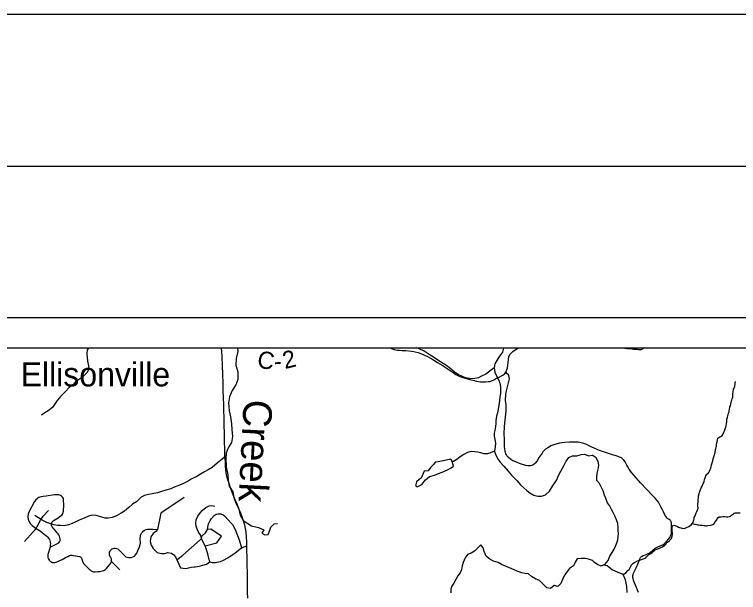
# Model space of a CAD drawing. Extents: x 0 to 34, y 0 to 22.
# Drawn here: x 3.746 to 6.132, y 20.093 to 22 of the extents above; entities that cross this region are included whole.
import ezdxf

# ---------------------------------------------------------------- set-up
doc = ezdxf.new("R2010")
doc.units = 0
for name, color, linetype in [('GM_X_County_Road', 7, 'Continuous'), ('GM_X_County_Road_Text', 7, 'Continuous'), ('GM_X_Major_River', 7, 'Continuous'), ('GM_X_Minor_Lake', 7, 'Continuous'), ('GM_X_Minor_River', 7, 'Continuous'), ('GM_X_Minor_River_Text', 7, 'Continuous'), ('GM_X_State_Route', 7, 'Continuous'), ('GM_X_Township_Road', 7, 'Continuous'), ('GM_X_Unincorporated_Text', 7, 'Continuous'), ('SH_Border', 7, 'Continuous'), ('SH_Cut_Line', 7, 'Continuous'), ('SH_Data', 7, 'Continuous')]:
    doc.layers.add(name, color=color, linetype=linetype)

msp = doc.modelspace()

# ---------------------------------------------------------------- linework, layer by layer
at = {"layer": 'GM_X_County_Road'}
for points in [[(4.9846, 20.9), (4.9915, 20.8969), (4.9974, 20.895), (5.0027, 20.8939), (5.0086, 20.8928), (5.0149, 20.8923), (5.0229, 20.8916), (5.0355, 20.8912), (5.0545, 20.8896), (5.0625, 20.8884), (5.0663, 20.8874), (5.0767, 20.8846), (5.0881, 20.8804), (5.0956, 20.8768), (5.1075, 20.8713), (5.1251, 20.8619), (5.1406, 20.8524), (5.1554, 20.8434), (5.1692, 20.8341), (5.1922, 20.8187), (5.2011, 20.8128), (5.2123, 20.8072), (5.2174, 20.8045), (5.2239, 20.8022), (5.232, 20.7997), (5.2469, 20.7961), (5.2572, 20.7937)], [(5.3657, 20.8196), (5.3707, 20.8332), (5.374, 20.8613), (5.3757, 20.8718), (5.3799, 20.8799), (5.3884, 20.8884), (5.4057, 20.9)], [(5.2572, 20.7937), (5.2693, 20.7908), (5.2759, 20.7894), (5.282, 20.7883), (5.2905, 20.7876), (5.2987, 20.7882), (5.3072, 20.7888), (5.3127, 20.7894), (5.3211, 20.7924), (5.3281, 20.796), (5.335, 20.7997), (5.3367, 20.8004), (5.3552, 20.8104), (5.36, 20.8133), (5.3624, 20.8155), (5.3657, 20.8196)], [(5.9114, 20.3196), (5.9114, 20.3205), (5.9112, 20.3228), (5.9107, 20.3248), (5.91, 20.327), (5.9088, 20.3293), (5.9071, 20.3316), (5.9041, 20.334), (5.8993, 20.3363), (5.8971, 20.3387), (5.8942, 20.3423), (5.891, 20.3463), (5.8892, 20.3492), (5.8847, 20.3593), (5.8816, 20.3661), (5.8778, 20.3738), (5.8723, 20.3844), (5.8682, 20.3908), (5.8633, 20.3979), (5.8576, 20.4047), (5.8495, 20.4127), (5.8317, 20.4317), (5.8094, 20.4547), (5.7881, 20.4788), (5.7808, 20.4879), (5.776, 20.4939), (5.7718, 20.5003), (5.7682, 20.5072), (5.7647, 20.5131), (5.7585, 20.5237), (5.7547, 20.5292), (5.7519, 20.5324), (5.747, 20.537), (5.7436, 20.5385), (5.733, 20.5428), (5.7256, 20.5449), (5.7209, 20.5465), (5.6904, 20.556), (5.6745, 20.5614), (5.6488, 20.5728), (5.6288, 20.5821), (5.6225, 20.5845), (5.6179, 20.5861), (5.6142, 20.5872), (5.6092, 20.5883), (5.6035, 20.5888), (5.5959, 20.5895), (5.5892, 20.5895), (5.5802, 20.5892), (5.575, 20.5892), (5.5599, 20.5883), (5.5503, 20.5871), (5.5421, 20.5857), (5.5303, 20.5827), (5.52, 20.5793), (5.5144, 20.5771), (5.5092, 20.5741), (5.5038, 20.5707), (5.4968, 20.5656), (5.4943, 20.5634), (5.4879, 20.5568), (5.4848, 20.5533), (5.4759, 20.5398), (5.4683, 20.5275), (5.4626, 20.5202), (5.4589, 20.5163), (5.4554, 20.5139), (5.4513, 20.5121), (5.4467, 20.5113), (5.4413, 20.5109), (5.4377, 20.5111), (5.4312, 20.512), (5.4285, 20.5128), (5.4235, 20.5143), (5.4111, 20.5185), (5.4002, 20.5227), (5.3926, 20.5261), (5.3885, 20.5279), (5.3823, 20.5315), (5.3732, 20.5395), (5.3701, 20.5432), (5.3678, 20.5471), (5.3659, 20.5508), (5.3646, 20.5553), (5.3633, 20.5606), (5.3625, 20.5666), (5.3617, 20.5735), (5.3613, 20.5986), (5.3596, 20.6163), (5.3611, 20.6413), (5.3671, 20.6921), (5.3664, 20.7134), (5.3644, 20.7271), (5.366, 20.7479), (5.3677, 20.7585), (5.3731, 20.7802), (5.3772, 20.7984), (5.377, 20.8035), (5.3756, 20.8074), (5.374, 20.8114), (5.3697, 20.814), (5.3657, 20.8196)], [(5.8033, 20.093), (5.7996, 20.1007), (5.7957, 20.1095), (5.7928, 20.1169), (5.7896, 20.1252), (5.7875, 20.131), (5.7864, 20.1342), (5.785, 20.1391), (5.7843, 20.1432), (5.7843, 20.1467), (5.7846, 20.1496), (5.785, 20.1528), (5.7862, 20.1565), (5.788, 20.1611), (5.7948, 20.1741), (5.803, 20.1917), (5.8077, 20.2039), (5.8097, 20.2082), (5.811, 20.21), (5.8127, 20.2117), (5.8148, 20.2129), (5.8182, 20.2148), (5.8259, 20.2174), (5.8282, 20.2183), (5.8345, 20.2214), (5.8361, 20.2222), (5.8424, 20.2266), (5.8572, 20.2398), (5.864, 20.243), (5.8764, 20.2481), (5.8833, 20.2509), (5.888, 20.2545), (5.8941, 20.2599), (5.902, 20.2688), (5.9061, 20.275), (5.9088, 20.2788), (5.9098, 20.2821), (5.9109, 20.2849), (5.9115, 20.2883), (5.9117, 20.292), (5.9115, 20.299), (5.9118, 20.311), (5.9114, 20.3196)]]:
    msp.add_lwpolyline(points, dxfattribs=at)
at = {"layer": 'GM_X_Major_River'}
for points in [[(5.358, 20.9), (5.3579, 20.8993), (5.3542, 20.8864), (5.3447, 20.8728), (5.336, 20.8587), (5.3288, 20.847), (5.3269, 20.8345), (5.3288, 20.8204), (5.3349, 20.8079), (5.3424, 20.7939), (5.3458, 20.7837), (5.3477, 20.7711), (5.3485, 20.7609), (5.3477, 20.7495), (5.3458, 20.7389), (5.3447, 20.7271), (5.3435, 20.7169), (5.3398, 20.6979), (5.3379, 20.6858), (5.3352, 20.6748), (5.3329, 20.6608), (5.3329, 20.6505), (5.3314, 20.6411), (5.3291, 20.6278), (5.3269, 20.6183), (5.3273, 20.6084), (5.3288, 20.5982), (5.331, 20.5853), (5.3299, 20.5739), (5.328, 20.5599), (5.3318, 20.5497), (5.3386, 20.5349), (5.3458, 20.5239), (5.359, 20.5099), (5.373, 20.4936), (5.3843, 20.4807), (5.4021, 20.4632), (5.4138, 20.4484), (5.4251, 20.4386), (5.4349, 20.4302), (5.4451, 20.4215), (5.4576, 20.4143), (5.4705, 20.4113), (5.4833, 20.4109), (5.4958, 20.4159), (5.509, 20.4272), (5.5189, 20.4436), (5.5276, 20.4553), (5.5332, 20.4648), (5.5397, 20.4788), (5.5472, 20.4933), (5.5521, 20.5035), (5.5574, 20.513), (5.5642, 20.5266), (5.5729, 20.5384), (5.5854, 20.5437), (5.5994, 20.5441), (5.6134, 20.5483), (5.6251, 20.549), (5.6376, 20.5445), (5.6504, 20.546)], [(5.6507, 20.1983), (5.6547, 20.1954), (5.6688, 20.1852), (5.679, 20.1815), (5.6924, 20.1856), (5.7026, 20.1983), (5.7087, 20.2129), (5.7159, 20.2256), (5.7223, 20.2361), (5.7275, 20.2458), (5.7316, 20.2567), (5.7342, 20.2665), (5.736, 20.2767), (5.7367, 20.2881), (5.7362, 20.298), (5.7354, 20.3079), (5.7342, 20.3204), (5.7307, 20.3327), (5.7243, 20.3462), (5.7193, 20.3569), (5.7142, 20.3669), (5.7073, 20.3797), (5.7008, 20.3893), (5.6966, 20.4012), (5.6905, 20.4147), (5.6859, 20.4285), (5.6813, 20.44), (5.6744, 20.4528), (5.666, 20.4629), (5.6659, 20.4727), (5.667, 20.4871), (5.6701, 20.5003), (5.6716, 20.5132), (5.67, 20.5258), (5.6628, 20.5378), (5.6504, 20.546)], [(5.6507, 20.1983), (5.6379, 20.2032), (5.6265, 20.2058), (5.6137, 20.2058), (5.6008, 20.2039), (5.5944, 20.1937), (5.5884, 20.1815), (5.5759, 20.1728), (5.5642, 20.1584), (5.5581, 20.1485), (5.5524, 20.136), (5.5468, 20.1231), (5.5373, 20.1133), (5.5245, 20.1163), (5.5131, 20.1064), (5.5003, 20.1091), (5.4765, 20.1329), (5.4632, 20.1379), (5.4504, 20.1458), (5.4398, 20.1549), (5.4277, 20.1557), (5.4179, 20.1576), (5.4028, 20.164), (5.3929, 20.1682), (5.3782, 20.175), (5.365, 20.1799), (5.3514, 20.186), (5.3408, 20.1924), (5.3249, 20.197), (5.3132, 20.2034), (5.3011, 20.2133), (5.2943, 20.2284), (5.2913, 20.2402), (5.2833, 20.2508), (5.2716, 20.2387), (5.2622, 20.2292), (5.2516, 20.2231), (5.2395, 20.2185), (5.2319, 20.2075), (5.2251, 20.1924), (5.2213, 20.1814), (5.2198, 20.1685), (5.2149, 20.1582), (5.2073, 20.1484), (5.2013, 20.1366), (5.1945, 20.1245), (5.1877, 20.1138), (5.1846, 20.104), (5.1846, 20.0926)]]:
    msp.add_lwpolyline(points, dxfattribs=at)
at = {"layer": 'GM_X_Minor_Lake'}
for points in [[(5.1887, 20.525), (5.1838, 20.533), (5.1592, 20.5278), (5.143, 20.524), (5.1331, 20.5233), (5.1278, 20.5161), (5.1187, 20.5063), (5.1092, 20.4942), (5.0963, 20.4935), (5.0898, 20.4776), (5.0868, 20.4704), (5.0804, 20.4662), (5.0713, 20.4579), (5.0686, 20.4496), (5.0686, 20.4435), (5.0731, 20.4416)], [(5.0731, 20.4416), (5.089, 20.4491), (5.1012, 20.4646), (5.1137, 20.4756), (5.13, 20.4808), (5.1436, 20.4861), (5.1557, 20.4898), (5.1732, 20.4977), (5.1853, 20.5045), (5.1929, 20.5102), (5.1887, 20.525)]]:
    msp.add_lwpolyline(points, dxfattribs=at)
at = {"layer": 'GM_X_Minor_River'}
for points in [[(3.9908, 20.9), (3.9858, 20.8937), (3.985, 20.8808), (3.9854, 20.8687), (3.9865, 20.8562), (3.9903, 20.8406), (3.9911, 20.8296), (3.985, 20.8175), (3.9699, 20.8035), (3.9601, 20.7966), (3.9472, 20.7879), (3.9381, 20.7777), (3.9268, 20.7697), (3.9147, 20.7568), (3.9034, 20.745), (3.8943, 20.7355), (3.8867, 20.7261), (3.878, 20.7139), (3.8712, 20.7037), (3.8576, 20.6923), (3.8463, 20.6858), (3.8349, 20.6779)], [(4.4816, 20.9), (4.4822, 20.8884), (4.4772, 20.8648), (4.476, 20.8432), (4.482, 20.8211), (4.4827, 20.796), (4.4755, 20.7782), (4.4633, 20.7599), (4.4546, 20.7386), (4.4511, 20.7185), (4.4537, 20.693), (4.4586, 20.6725), (4.4615, 20.6493), (4.4626, 20.6314), (4.4645, 20.6078), (4.4618, 20.5884), (4.4504, 20.5709), (4.4443, 20.5531), (4.4424, 20.5348), (4.4438, 20.5082), (4.449, 20.4812), (4.4509, 20.4626), (4.4543, 20.4439), (4.4656, 20.4253), (4.4693, 20.407), (4.4757, 20.388), (4.4851, 20.3682), (4.4896, 20.3488), (4.5002, 20.3302)], [(5.3269, 20.8345), (5.2997, 20.8136), (5.2853, 20.8064), (5.2751, 20.8018), (5.2634, 20.7988), (5.2506, 20.798), (5.2328, 20.8018), (5.223, 20.8052), (5.2082, 20.8128), (5.1961, 20.8204), (5.1795, 20.834), (5.164, 20.8458), (5.1447, 20.8579), (5.1304, 20.8677), (5.113, 20.8787), (5.096, 20.889), (5.0801, 20.8973), (5.072, 20.9)], [(5.8215, 20.9), (5.8212, 20.8997), (5.8166, 20.8975), (5.8132, 20.8953), (5.8101, 20.8942), (5.8071, 20.8939), (5.8029, 20.8939), (5.7984, 20.8951), (5.7939, 20.8945), (5.7908, 20.8949), (5.7867, 20.8953), (5.7821, 20.8958), (5.7765, 20.8967), (5.7704, 20.8975), (5.764, 20.8969), (5.7583, 20.8985), (5.7515, 20.8997), (5.7497, 20.9)], [(6.0553, 20.5581), (6.0562, 20.5611), (6.0566, 20.5649), (6.0574, 20.5683), (6.0583, 20.5725), (6.0595, 20.5762), (6.0603, 20.5789), (6.0615, 20.5868), (6.062, 20.5906), (6.0624, 20.5933), (6.0632, 20.5959), (6.0648, 20.6023), (6.0675, 20.6046), (6.0714, 20.6064), (6.0775, 20.609), (6.0813, 20.6146), (6.0845, 20.6225), (6.0865, 20.6267), (6.0885, 20.6327), (6.0905, 20.6391), (6.0921, 20.6429), (6.0926, 20.6494), (6.0935, 20.6573), (6.0935, 20.6622), (6.094, 20.6653), (6.0964, 20.6709), (6.0972, 20.6766), (6.0984, 20.6793), (6.0996, 20.6849), (6.1012, 20.6895), (6.1016, 20.6921), (6.1029, 20.697), (6.1042, 20.7054), (6.1057, 20.7091), (6.1073, 20.714), (6.1086, 20.7201), (6.1098, 20.725), (6.1106, 20.7277), (6.1115, 20.7326), (6.1138, 20.7375), (6.1135, 20.7409), (6.1136, 20.7443), (6.114, 20.7485), (6.1149, 20.7557), (6.1162, 20.7636), (6.1177, 20.7667), (6.1201, 20.7742), (6.1214, 20.7803), (6.1218, 20.7833), (6.1222, 20.7888)], [(5.3282, 20.5593), (5.3148, 20.5541), (5.3054, 20.5507), (5.2936, 20.5508), (5.2827, 20.5538), (5.2717, 20.5565), (5.2619, 20.5573), (5.2517, 20.5578), (5.2392, 20.5548), (5.2267, 20.548), (5.2153, 20.5404), (5.2039, 20.5318), (5.1929, 20.5254), (5.1887, 20.525)], [(5.752, 20.1528), (5.7612, 20.1582), (5.7682, 20.1657), (5.7724, 20.1687), (5.7743, 20.1732), (5.7783, 20.1811), (5.7791, 20.1837), (5.7826, 20.1882), (5.7883, 20.1923), (5.7917, 20.1934), (5.799, 20.1978), (5.8074, 20.2), (5.8127, 20.2018), (5.8211, 20.2058), (5.8242, 20.2061), (5.8265, 20.2091), (5.8357, 20.217), (5.8438, 20.2214), (5.8476, 20.2247), (5.8515, 20.2288), (5.8541, 20.2303), (5.8572, 20.2337), (5.8629, 20.2359), (5.8721, 20.2395), (5.879, 20.2428), (5.882, 20.2435), (5.8901, 20.2498), (5.8986, 20.2588), (5.9051, 20.2636), (5.9063, 20.2663), (5.9117, 20.2711), (5.9141, 20.2791), (5.9145, 20.2836), (5.915, 20.287), (5.9147, 20.2904), (5.914, 20.2958), (5.9137, 20.3007), (5.9138, 20.3064), (5.9142, 20.3102), (5.9151, 20.3136), (5.9193, 20.315), (5.926, 20.3134), (5.9309, 20.311), (5.9351, 20.3087), (5.946, 20.3055), (5.9535, 20.3042), (5.957, 20.3053), (5.9612, 20.3071), (5.9684, 20.3104), (5.973, 20.3145), (5.9773, 20.3179), (5.98, 20.3205), (5.9815, 20.3231), (5.9831, 20.3261), (5.9843, 20.3299), (5.9851, 20.3325), (5.9859, 20.3356), (5.9868, 20.3409), (5.9899, 20.3465), (5.9903, 20.3492), (5.9927, 20.356), (5.9947, 20.3601), (5.9978, 20.3657), (5.9986, 20.3684), (5.999, 20.371), (5.9984, 20.3786), (5.9988, 20.3813), (5.9991, 20.3953), (5.9991, 20.3991), (6.0001, 20.4082), (6.0009, 20.4116), (6.0025, 20.4196), (6.0041, 20.4237), (6.0049, 20.4264), (6.0057, 20.4294), (6.0089, 20.4385), (6.0128, 20.4445), (6.0156, 20.4524), (6.0176, 20.4558), (6.0188, 20.4596), (6.0204, 20.4656), (6.0216, 20.4686), (6.0236, 20.4747), (6.0244, 20.4785), (6.0283, 20.4833), (6.0313, 20.4852), (6.0341, 20.4889), (6.0364, 20.4935), (6.0392, 20.4991), (6.0411, 20.5036), (6.0432, 20.5138), (6.0444, 20.5176), (6.0464, 20.5237), (6.0476, 20.5274), (6.048, 20.5301), (6.0501, 20.5369), (6.0517, 20.5445), (6.0529, 20.5471), (6.0541, 20.552), (6.0553, 20.5554), (6.0553, 20.5581)], [(4.4424, 20.5348), (4.4423, 20.5428), (4.4302, 20.5329), (4.4147, 20.5196), (4.3981, 20.5056), (4.3849, 20.498), (4.372, 20.4908), (4.3588, 20.4832), (4.3475, 20.4764), (4.3289, 20.4676), (4.3187, 20.4604), (4.3036, 20.4532), (4.2843, 20.4449), (4.2722, 20.4403), (4.2616, 20.4357), (4.245, 20.4308), (4.2306, 20.4266), (4.2178, 20.4225), (4.2, 20.4186), (4.1875, 20.4167), (4.1747, 20.4137), (4.1634, 20.408), (4.1482, 20.3928), (4.1354, 20.3841), (4.1233, 20.3731), (4.1093, 20.3613), (4.0983, 20.3549), (4.0828, 20.3462), (4.0677, 20.3405), (4.0552, 20.3386), (4.045, 20.3389), (4.031, 20.3427), (4.0155, 20.3476), (4.0027, 20.348), (3.9906, 20.345), (3.9762, 20.3389), (3.9596, 20.3313), (3.946, 20.3248), (3.9358, 20.321), (3.9237, 20.3169), (3.9097, 20.3134), (3.898, 20.3138), (3.8878, 20.3138), (3.8764, 20.3161), (3.8655, 20.3195), (3.853, 20.3237), (3.8379, 20.332), (3.825, 20.3396), (3.8137, 20.3475)], [(5.98, 20.3205), (5.9879, 20.3184), (5.9905, 20.3188), (5.9947, 20.3176), (5.9981, 20.3167), (6.0022, 20.3159), (6.0056, 20.3155), (6.0083, 20.3154), (6.0124, 20.315), (6.0181, 20.3141), (6.0219, 20.3144), (6.0249, 20.3136), (6.0276, 20.3136), (6.0317, 20.3143), (6.0412, 20.3156), (6.0511, 20.3189), (6.0566, 20.3271), (6.0609, 20.3328), (6.0617, 20.3358), (6.0648, 20.3399), (6.0682, 20.3425), (6.0732, 20.3432), (6.0758, 20.3431), (6.0804, 20.3434), (6.0834, 20.3438), (6.086, 20.3437), (6.0913, 20.3433), (6.0974, 20.3432), (6.1031, 20.3438), (6.1065, 20.3453), (6.1092, 20.3479), (6.1127, 20.3505), (6.1154, 20.3531), (6.1184, 20.3553), (6.1211, 20.3564), (6.1294, 20.3559), (6.1382, 20.3558)], [(4.5002, 20.3302), (4.527, 20.3131), (4.5505, 20.3081), (4.5676, 20.3004)], [(4.5676, 20.3004), (4.5614, 20.2887), (4.5716, 20.2834), (4.5822, 20.2841), (4.5879, 20.2993), (4.591, 20.3087), (4.602, 20.3201), (4.613, 20.3204), (4.6126, 20.3208)], [(5.7647, 20.1126), (5.7595, 20.1353), (5.752, 20.1528), (5.7338, 20.1604), (5.7165, 20.1681), (5.6991, 20.181), (5.6879, 20.1842)], [(5.7654, 20.0928), (5.7647, 20.1126)]]:
    msp.add_lwpolyline(points, dxfattribs=at)
at = {"layer": 'GM_X_State_Route'}
for points in [[(4.4349, 20.7402), (4.4345, 20.7551), (4.4339, 20.7845), (4.4328, 20.8108), (4.4322, 20.8435), (4.4312, 20.8696), (4.4293, 20.8903), (4.4274, 20.9)], [(4.5153, 20.0743), (4.5146, 20.0938), (4.5138, 20.145), (4.5131, 20.1979), (4.5128, 20.2081), (4.5123, 20.2323), (4.5119, 20.2476), (4.5116, 20.2589), (4.5107, 20.2767), (4.5093, 20.2922), (4.5073, 20.3044), (4.505, 20.3152), (4.5012, 20.3292), (4.4975, 20.3396), (4.4932, 20.3515), (4.487, 20.3669), (4.4808, 20.3825), (4.474, 20.399), (4.4607, 20.4321), (4.4522, 20.4556), (4.4491, 20.4652), (4.4462, 20.4772), (4.4444, 20.4876), (4.4431, 20.4975), (4.442, 20.5085), (4.4415, 20.5235), (4.44, 20.5478), (4.4384, 20.6094), (4.4376, 20.6544), (4.4357, 20.7093), (4.4349, 20.7402)]]:
    msp.add_lwpolyline(points, dxfattribs=at)
at = {"layer": 'GM_X_Township_Road'}
for p, q in [((3.7789, 20.2616), (3.8178, 20.3042)), ((4.0659, 20.195), (4.0936, 20.1682))]:
    msp.add_line(p, q, dxfattribs=at)
for points in [[(3.8636, 20.2431), (3.8919, 20.2574), (3.8948, 20.2603), (3.8964, 20.2647), (3.8964, 20.2702), (3.8957, 20.2742), (3.8943, 20.2788), (3.8925, 20.2832), (3.8904, 20.2867), (3.8872, 20.2904), (3.8837, 20.2946), (3.8774, 20.3016), (3.8736, 20.3057), (3.8713, 20.3084), (3.8697, 20.3111), (3.8687, 20.3143), (3.8685, 20.317), (3.8685, 20.3203), (3.8696, 20.3235), (3.8709, 20.3262), (3.8733, 20.3294), (3.8766, 20.3313), (3.8897, 20.3399), (3.8967, 20.3446), (3.902, 20.3483), (3.9058, 20.3537), (3.9083, 20.3612), (3.909, 20.3826), (3.9081, 20.398), (3.9074, 20.403), (3.9047, 20.4078), (3.9015, 20.4112), (3.8981, 20.4135), (3.8922, 20.4155), (3.8879, 20.4157), (3.8833, 20.4157), (3.8783, 20.4157), (3.8504, 20.411), (3.8404, 20.4094), (3.8341, 20.4085), (3.8302, 20.4073), (3.8268, 20.4062), (3.8234, 20.4044), (3.8207, 20.4026), (3.817, 20.3989), (3.8125, 20.3932), (3.7948, 20.3601), (3.7916, 20.3524), (3.7902, 20.3426), (3.7911, 20.3351), (3.7941, 20.3265), (3.7982, 20.3208), (3.8047, 20.3143), (3.8178, 20.3042), (3.8311, 20.2961), (3.8371, 20.2911), (3.8432, 20.2866), (3.8489, 20.2821), (3.8524, 20.2791), (3.8558, 20.2758), (3.8585, 20.2724), (3.8611, 20.2677), (3.863, 20.2635), (3.8641, 20.2589), (3.8646, 20.2539), (3.8641, 20.2491), (3.8636, 20.2431), (3.8566, 20.2189), (3.8561, 20.2159), (3.8557, 20.213), (3.8561, 20.2096), (3.8573, 20.2049), (3.8601, 20.2), (3.8636, 20.1964), (3.8659, 20.195), (3.8689, 20.1935), (3.8718, 20.1927), (3.8755, 20.192), (3.8795, 20.1923), (3.8832, 20.193), (3.8895, 20.1959), (3.8952, 20.1989), (3.9033, 20.2026), (3.9142, 20.2084), (3.9219, 20.2125), (3.9277, 20.2149), (3.9312, 20.216), (3.9348, 20.2161), (3.9384, 20.2158), (3.9405, 20.2154), (3.9481, 20.214), (3.9542, 20.2133), (3.96, 20.2125), (3.9633, 20.2105), (3.9656, 20.2084), (3.9677, 20.2047), (3.9709, 20.1967), (3.9738, 20.1891), (3.981, 20.1809), (3.9923, 20.1703), (3.9956, 20.1675), (3.9989, 20.1647), (4.0033, 20.1623), (4.007, 20.1614), (4.0126, 20.1611), (4.0207, 20.1621), (4.0287, 20.163), (4.0361, 20.1642), (4.041, 20.166), (4.0457, 20.1688), (4.0489, 20.1718), (4.0549, 20.1786), (4.0606, 20.1856), (4.064, 20.1898), (4.0659, 20.195), (4.0664, 20.1999), (4.0657, 20.204), (4.0635, 20.2086), (4.0618, 20.2114), (4.0603, 20.2143), (4.0594, 20.217), (4.0589, 20.22), (4.0592, 20.2238), (4.0598, 20.2267), (4.0611, 20.2294), (4.0628, 20.232), (4.0645, 20.2341), (4.0664, 20.2359), (4.0683, 20.2371), (4.0713, 20.2383), (4.0747, 20.2393), (4.0781, 20.2395), (4.0819, 20.2388), (4.0863, 20.2371), (4.0903, 20.2339), (4.0935, 20.231), (4.1005, 20.2238), (4.1097, 20.2145), (4.1137, 20.2113), (4.1181, 20.2094), (4.1227, 20.2085), (4.1307, 20.2083), (4.1368, 20.2105), (4.1419, 20.2134), (4.1453, 20.2171), (4.1491, 20.2227), (4.1525, 20.2314), (4.1582, 20.2443), (4.1615, 20.2555), (4.1611, 20.2588), (4.1608, 20.2665), (4.1609, 20.2725), (4.161, 20.2774), (4.1618, 20.2811), (4.1629, 20.2844), (4.1652, 20.2887), (4.1679, 20.2924), (4.1706, 20.2954), (4.1744, 20.2983), (4.1802, 20.3011), (4.1844, 20.3022), (4.1906, 20.3025), (4.2035, 20.3019), (4.2177, 20.301)], [(4.3055, 20.4061), (4.229, 20.3545), (4.2177, 20.301), (4.2116, 20.2949), (4.2033, 20.2873), (4.1952, 20.2771), (4.193, 20.2611), (4.1971, 20.2489), (4.2032, 20.2387), (4.2164, 20.2257), (4.2305, 20.2219), (4.2416, 20.2219), (4.2515, 20.225), (4.264, 20.2231), (4.2718, 20.217), (4.2764, 20.2105), (4.2815, 20.201), (4.2881, 20.1865), (4.2939, 20.1741), (4.3111, 20.1729), (4.329, 20.1771), (4.3381, 20.178)], [(4.3581, 20.2847), (4.3526, 20.2927), (4.3479, 20.3023), (4.3449, 20.3116), (4.3439, 20.322), (4.3455, 20.3331), (4.3502, 20.3445), (4.3592, 20.3574), (4.3647, 20.3636), (4.3774, 20.3733), (4.388, 20.3788), (4.3953, 20.3802), (4.4066, 20.3781)], [(3.8178, 20.3042), (3.8219, 20.3134), (3.8315, 20.3317), (3.8413, 20.3451), (3.8588, 20.3637)], [(4.2815, 20.201), (4.3009, 20.2166), (4.3586, 20.2672), (4.3627, 20.2711), (4.3647, 20.2803), (4.3753, 20.2904), (4.3822, 20.301), (4.3836, 20.3089), (4.3857, 20.3195), (4.3907, 20.3307), (4.396, 20.3369), (4.4043, 20.3471), (4.4114, 20.3512), (4.4179, 20.3531), (4.4264, 20.3528), (4.4335, 20.3493), (4.4395, 20.3451), (4.4506, 20.3329), (4.4604, 20.3224), (4.465, 20.317), (4.4737, 20.3006), (4.487, 20.2672), (4.4943, 20.2409)], [(4.3901, 20.1946), (4.3866, 20.2051), (4.383, 20.2213), (4.3745, 20.2472), (4.3683, 20.2591), (4.3627, 20.2711), (4.3609, 20.2807), (4.3581, 20.2847)], [(4.3745, 20.2472), (4.4127, 20.2573), (4.429, 20.2795), (4.3929, 20.3021), (4.3822, 20.301)], [(4.3381, 20.178), (4.3421, 20.1784), (4.3547, 20.1803), (4.3795, 20.1866), (4.3901, 20.1946), (4.3981, 20.1923), (4.4072, 20.1919), (4.4255, 20.1953), (4.435, 20.1995), (4.449, 20.2075), (4.4737, 20.2242), (4.4943, 20.2409), (4.5119, 20.2476)]]:
    msp.add_lwpolyline(points, dxfattribs=at)
at = {"layer": 'SH_Border'}
msp.add_lwpolyline([(1.5, 21.5), (33.5, 21.5), (33.5, 0.5), (1.5, 0.5)], close=True, dxfattribs=at)
at = {"layer": 'SH_Cut_Line'}
msp.add_lwpolyline([(0, 0), (34, 0), (34, 22), (0, 22)], close=True, dxfattribs=at)
at = {"layer": 'SH_Data'}
for p, q in [((2, 21), (9, 21)), ((2.1, 20.9), (8.9, 20.9))]:
    msp.add_line(p, q, dxfattribs=at)

# ---------------------------------------------------------------- texts
at = {"layer": 'GM_X_County_Road_Text'}
for s, rotation, p in [('C', 350.4761, (4.5434, 20.8359)), ('2', 13.542, (4.6375, 20.8301)), ('-', 2.4668, (4.6023, 20.8274))]:
    msp.add_text(s, height=0.0568, rotation=rotation, dxfattribs=at).set_placement(p)
at = {"layer": 'GM_X_Minor_River_Text'}
msp.add_text('Creek', height=0.09468, rotation=267.0459, dxfattribs=at).set_placement((4.502, 20.7313))
at = {"layer": 'GM_X_Unincorporated_Text'}
msp.add_text('Ellisonville', height=0.078977, rotation=0, dxfattribs=at).set_placement((3.7663, 20.7731))

doc.saveas('drawing.dxf')
